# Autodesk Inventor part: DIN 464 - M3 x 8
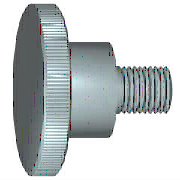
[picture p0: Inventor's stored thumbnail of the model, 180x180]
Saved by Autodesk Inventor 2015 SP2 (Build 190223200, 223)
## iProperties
Created: 2014-02
Part Number: DIN 464 - M3 x 8
Material: Stahl, weich
Description: Rändelschraube
Document SubType Name: Modeling
Standard: DIN 464
Designer: rYan
Standards Organization: DIN
Language: de-DE
Size Designation: M3 x 8
Categories: <MemberInstance><Categories><Category DisplayName="Verbindungselemente" InternalName="e4da775c-781d-43d5-af7c-5136215cf5a6" Mnemonic="FSTN"><Category DisplayNam
Density: 7.85 g/cm^3
Appearance: Halbpoliert
IsCustomPart: 0
Author: rYan
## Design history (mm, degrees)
revolve "Körper" stored, may be unused: angle "d8" = 90 deg
node "IDS_WORKPLANE{1}"
workplane "Work Plane2"
body "Solid1"
feature "Gewinde" dims "d2" = 6.724 (= GEL - 0.092 x GD), "d3" = 0
chamfer "Fase1" distance "d10" = 0.3 (= PHH); stored, may be unused: angle "d11" = 45 deg (= FAWI), second distance "d38" = 0.3 (= PHH)
sketch "Skizze1"
  geometry: L1 (-7.5, 0)-(8, 0); L2 (8, 0)-(8, 5); L3 (7.673, 1.5)-(0, 1.5); L4 (0, 1.5)-(0, 3); L5 (0, -1.2)-(0, 7.2) reference; L6 (0, 3)-(-5, 3); L7 (-5, 3)-(-5, 6); L8 (-5, 6)-(-7.5, 6); L9 (-7.5, 6)-(-7.5, 0); L10 (-10.616, 0)-(11.197, 0) reference; A1 r 3.6 centre (4.4, 0) between (8, 0) and (7.673, 1.5)
  constraints: 16 end point, 3 parallel, 3 perpendicular, 2 collinear, 2 point on circle, 2 vertical alignment, 1 centre point, 1 midpoint, 1 point on line, 1 tangent
  dimensions: "d0" = 8 distance between parallel lines of L2 L4 (= NLG); "d1" = 3 diameter of L3 L1 (= GD); "d5" = 6 diameter of L6 L1 (= LADI); "d6" = 12 diameter of L8 L1 (= KOD); "d7" = 2.5 distance between parallel lines of L7 L9 (= KOH); "d9" = 3.6 radius of A1 (= 1.2 x GD); "d19" = 7.5 distance between parallel lines of L4 L9 (= KOH + SD)
other parameters: "GD" = 3 (= NND) [user parameter; used in 3 equation terms], "NLG" = 8 [user parameter; used in 1 equation term], "GEL" = 7 [user parameter; used in 1 equation term], "KOD" = 12 [user parameter; used in 1 equation term], "KOH" = 2.5 [user parameter; used in 3 equation terms], "GAL" = 0.30673 (= 0.61345 x PTC) [user parameter], "d4" = 0, "SD" = 5 [user parameter; used in 1 equation term], "LADI" = 6 [user parameter; used in 1 equation term], "PHH" = 0.3 [user parameter; used in 2 equation terms], "FAWI" = 45 deg [user parameter; used in 1 equation term], "d12" = -1.25 (= -0.5 x KOH), "T" = 0.5 [user parameter], "d39" = 0, "d40" = 0, "PTC" = 0.5 [user parameter; used in 2 equation terms], "NND" = 3 [user parameter; used in 1 equation term]
